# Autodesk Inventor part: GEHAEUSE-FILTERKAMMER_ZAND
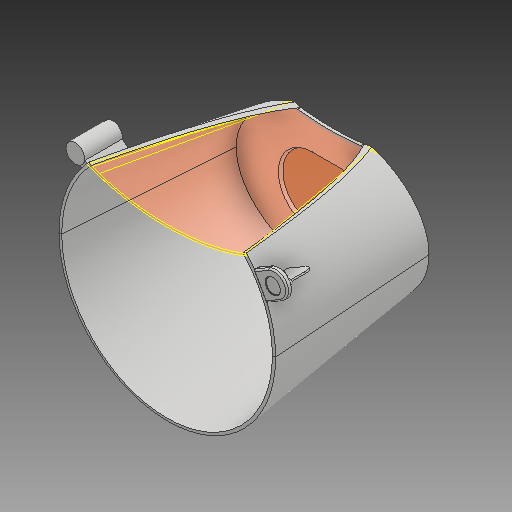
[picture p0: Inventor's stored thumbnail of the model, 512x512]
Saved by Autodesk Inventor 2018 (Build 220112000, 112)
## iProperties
Created: 2019-01
Part Number: GEHAEUSE-FILTERKAMMER_ZAND
Material: Polypropylene (PP)
Document SubType Name: Modeling
Designer: zand
Density: 0.902188 g/cm^3
Appearance: Vorgabe
Mass: 75.6585 g
Surface Area: 879.599 cm^2
Volume: 83.8611 cm^3
Author: zand
Revision Number: 21LAST_VERSION
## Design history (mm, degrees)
feature "Basis1"
feature "Basis2"
feature "Zusammengesetzt1"
node "Volumenkörper1"
node "Volumenkörper2"
node "Flä1"
